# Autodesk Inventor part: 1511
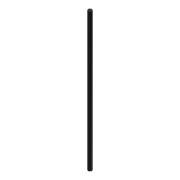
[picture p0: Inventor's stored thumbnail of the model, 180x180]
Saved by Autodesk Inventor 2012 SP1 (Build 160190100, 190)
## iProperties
Created: 2012-02
Part Number: 1511
Material: Silicone
Document SubType Name: Modeling
Designer: LACO
Density: 1.25 g/cm^3
Mass: 0.252259 g
Surface Area: 4.58976 cm^2
Volume: 0.201807 cm^3
Author: LACO
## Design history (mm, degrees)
sketch "Sketch1"
  geometry: C1 r 0.889 at (0, 0); 1 further point
  constraints: 1 centre point, 1 coincident
  dimensions: "d0" = 1.778 dimension on point (0, 0) C1.centre C1; "d0" = 1.778 diameter of C1
extrude "Extrusion1" new body sketch "Sketch1" stored distance "d1" = 66.04; taper "d2" = 0 deg
body "Solid1"
